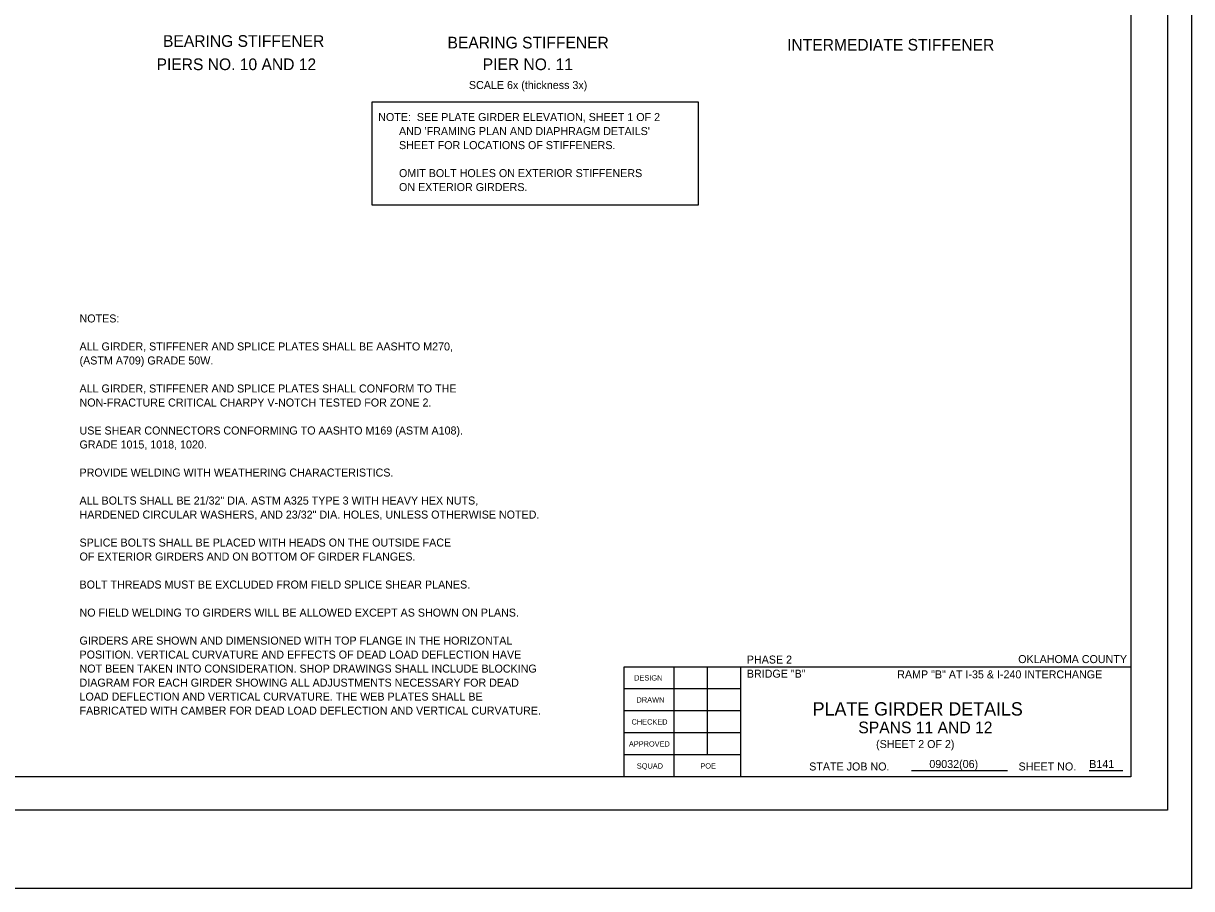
# Model space of a CAD drawing. Extents: x 4944 to 17449, y 3824 to 49087.
# Drawn here: x 8853 to 10535, y 38918 to 40163 of the extents above; entities that cross this region are included whole.
import ezdxf

# ---------------------------------------------------------------- set-up
doc = ezdxf.new("R2010")
doc.units = 0
for name, color, linetype in [('37_S_TXT', 7, 'Continuous'), ('3A', 7, 'Continuous'), ('BEAM', 7, 'Continuous'), ('DIM', 7, 'Continuous'), ('ID', 7, 'Continuous'), ('Level 14', 7, 'Continuous'), ('Level 17', 7, 'Continuous'), ('REVISED', 7, 'Continuous')]:
    doc.layers.add(name, color=color, linetype=linetype)

msp = doc.modelspace()

# ---------------------------------------------------------------- linework, layer by layer
at = {"layer": '37_S_TXT'}
msp.add_lwpolyline([(7079, 41222), (10535, 41222), (10535, 38917.9), (7079, 38917.9)], close=True, dxfattribs=at)
at = {"layer": '3A'}
msp.add_lwpolyline([(9354.5, 39902.3), (9825, 39902.3), (9825, 40049.8), (9354.5, 40049.8)], close=True, dxfattribs=at)
at = {"layer": 'DIM'}
msp.add_lwpolyline([(7236.2, 41142.8), (10500.2, 41142.8), (10500.2, 39030.7), (7236.2, 39030.7)], close=True, dxfattribs=at)
at = {"layer": 'Level 14'}
for p, q in [((9717.8, 39237.1), (10447.4, 39237.2)), ((9717.8, 39078.7), (9717.8, 39237.1)), ((9885.8, 39078.7), (9885.8, 39237.2)), ((9885.8, 39078.7), (9885.8, 39237.2))]:
    msp.add_line(p, q, dxfattribs=at)
msp.add_lwpolyline([(10447.4, 39078.7), (7423.4, 39078.7), (7423.4, 41094.8), (10447.4, 41094.8)], close=True, dxfattribs=at)
at = {"layer": 'Level 17'}
for p, q in [((9789.8, 39078.7), (9789.8, 39237.2)), ((9837.8, 39110.4), (9837.8, 39237.2)), ((10131.6, 39088), (10269.9, 39088)), ((10131.6, 39088), (10269.9, 39088)), ((10387.4, 39088), (10435.7, 39088)), ((10387.4, 39088), (10435.7, 39088))]:
    msp.add_line(p, q, dxfattribs=at)
for points in [[(9885.8, 39205.5), (9717.8, 39205.5)], [(9885.8, 39173.8), (9717.8, 39173.8)], [(9885.8, 39142.1), (9717.8, 39142.1)], [(9885.8, 39110.4), (9717.8, 39110.4)]]:
    msp.add_lwpolyline(points, dxfattribs=at)

# ---------------------------------------------------------------- texts
at = {"layer": '3A'}
for s, height, p in [('NOTE:  SEE PLATE GIRDER ELEVATION, SHEET 1 OF 2 ', 11.52, (9363.9, 40022.8)), ("       AND 'FRAMING PLAN AND DIAPHRAGM DETAILS' ", 11.52, (9363.9, 40002.6)), ('       SHEET FOR LOCATIONS OF STIFFENERS. ', 11.52, (9363.9, 39982.4)), ('       OMIT BOLT HOLES ON EXTERIOR STIFFENERS ', 11.52, (9363.9, 39942.1)), ('       ON EXTERIOR GIRDERS.', 11.52, (9363.9, 39922)), ('NOTES:', 11.52, (8933.9, 39732.9)), ('ALL GIRDER, STIFFENER AND SPLICE PLATES SHALL BE AASHTO M270,', 11.52, (8933.9, 39692.6)), ('(ASTM A709) GRADE 50W.', 11.52, (8933.9, 39672.4)), ('ALL GIRDER, STIFFENER AND SPLICE PLATES SHALL CONFORM TO THE', 11.52, (8933.9, 39632.1)), ('NON-FRACTURE CRITICAL CHARPY V-NOTCH TESTED FOR ZONE 2.', 11.52, (8933.9, 39611.9)), ('USE SHEAR CONNECTORS CONFORMING TO AASHTO M169 (ASTM A108).', 11.52, (8933.9, 39571.6)), ('GRADE 1015, 1018, 1020.', 11.52, (8933.9, 39551.5)), ('PROVIDE WELDING WITH WEATHERING CHARACTERISTICS.  ', 11.52, (8933.9, 39511.1)), ('ALL BOLTS SHALL BE 21/32" DIA. ASTM A325 TYPE 3 WITH HEAVY HEX NUTS, ', 11.52, (8933.9, 39470.8)), ('HARDENED CIRCULAR WASHERS, AND 23/32" DIA. HOLES, UNLESS OTHERWISE NOTED.  ', 11.52, (8933.9, 39450.6)), ('SPLICE BOLTS SHALL BE PLACED WITH HEADS ON THE OUTSIDE FACE', 11.52, (8933.9, 39410.3)), ('OF EXTERIOR GIRDERS AND ON BOTTOM OF GIRDER FLANGES.  ', 11.52, (8933.9, 39390.2)), ('BOLT THREADS MUST BE EXCLUDED FROM FIELD SPLICE SHEAR PLANES.', 11.52, (8933.9, 39349.9)), ('NO FIELD WELDING TO GIRDERS WILL BE ALLOWED EXCEPT AS SHOWN ON PLANS.', 11.52, (8933.9, 39309.5)), ('GIRDERS ARE SHOWN AND DIMENSIONED WITH TOP FLANGE IN THE HORIZONTAL', 11.52, (8933.9, 39269.2)), ('POSITION. VERTICAL CURVATURE AND EFFECTS OF DEAD LOAD DEFLECTION HAVE ', 11.52, (8933.9, 39249.1)), ('NOT BEEN TAKEN INTO CONSIDERATION. SHOP DRAWINGS SHALL INCLUDE BLOCKING ', 11.52, (8933.9, 39228.9)), ('PHASE 2', 11.52, (9894.6, 39241.9)), ('OKLAHOMA COUNTY', 11.52, (10285.3, 39242.6)), ('BRIDGE "B"', 11.52, (9894.6, 39221.6)), ('RAMP "B" AT I-35 & I-240 INTERCHANGE', 11.52, (10111.1, 39220.6)), ('DIAGRAM FOR EACH GIRDER SHOWING ALL ADJUSTMENTS NECESSARY FOR DEAD ', 11.52, (8933.9, 39208.7)), ('LOAD DEFLECTION AND VERTICAL CURVATURE. THE WEB PLATES SHALL BE ', 11.52, (8933.9, 39188.6)), ('FABRICATED WITH CAMBER FOR DEAD LOAD DEFLECTION AND VERTICAL CURVATURE.', 11.52, (8933.9, 39168.4)), ('(SHEET 2 OF 2)', 11.5, (10080.7, 39120.3)), ('09032(06)', 11.52, (10157.4, 39091.6)), ('B141', 11.52, (10387.6, 39091.6))]:
    msp.add_text(s, height=height, dxfattribs=at).set_placement(p)
at = {"layer": 'BEAM'}
for s, height, p in [('BEARING STIFFENER', 16.8, (9054.1, 40129.6)), ('BEARING STIFFENER', 16.8, (9463.7, 40127.3)), ('INTERMEDIATE STIFFENER', 16.8, (9952.6, 40124.2)), ('PIERS NO. 10 AND 12', 16.8, (9044.8, 40096.1)), ('PIER NO. 11', 16.8, (9514.4, 40096.1)), ('PLATE GIRDER DETAILS', 19.2, (9989.4, 39167.1))]:
    msp.add_text(s, height=height, dxfattribs=at).set_placement(p)
at = {"layer": 'DEFPOINTS'}
msp.add_text('SCALE 6x (thickness 3x)', height=11.52, dxfattribs=at).set_placement((9494.5, 40068.9))
at = {"layer": 'ID'}
msp.add_text('SPANS 11 AND 12', height=16.875, dxfattribs=at).set_placement((10055.1, 39141.5))
at = {"layer": 'REVISED'}
for s, height, p in [('DESIGN', 7.68, (9732.4, 39217.5)), ('DRAWN', 7.68, (9735.8, 39185.8)), ('CHECKED', 7.68, (9728.6, 39154.1)), ('APPROVED', 7.68, (9724.8, 39122.4)), ('SQUAD', 7.68, (9736.2, 39090.7)), ('POE', 7.68, (9827.7, 39090.7)), ('STATE JOB NO.', 11.52, (9984.4, 39088)), ('STATE JOB NO.', 11.52, (9984.4, 39088)), ('SHEET NO. ', 11.52, (10285.8, 39088)), ('SHEET NO. ', 11.52, (10285.8, 39088))]:
    msp.add_text(s, height=height, dxfattribs=at).set_placement(p)

doc.saveas('drawing.dxf')
